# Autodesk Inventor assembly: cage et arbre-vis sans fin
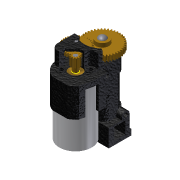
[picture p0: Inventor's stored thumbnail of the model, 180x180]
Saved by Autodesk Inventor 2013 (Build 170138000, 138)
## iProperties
Created: 2011-10
Part Number: cage et arbre-vis sans fin
Document SubType Name: Assembly
Designer: didierf
Author: didierf
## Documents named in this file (8)
- D:\_an13-14\FORMULAIRE_2014\Sujet E4 Poissy 2014\Modélisation_7970_shimano_2014\cage et arbre-vis sans fin.iam
- D:\_an13-14\FORMULAIRE_2014\Sujet E4 Poissy 2014\Modélisation_7970_shimano_2014\cage_moto_reducteur.ipt
- D:\_an13-14\FORMULAIRE_2014\Sujet E4 Poissy 2014\Modélisation_7970_shimano_2014\Mobile vis sans fin.iam
- D:\_an13-14\FORMULAIRE_2014\Sujet E4 Poissy 2014\Modélisation_7970_shimano_2014\Butée axiale vis sans fin.ipt
- D:\_an13-14\FORMULAIRE_2014\Sujet E4 Poissy 2014\Modélisation_7970_shimano_2014\axe engr_cyl inter.ipt
- D:\_an13-14\FORMULAIRE_2014\Sujet E4 Poissy 2014\Modélisation_7970_shimano_2014\Mobile intermédiaire 37 dents m0,25 - 10 dents m0,3.iam
- D:\_an13-14\FORMULAIRE_2014\Sujet E4 Poissy 2014\Modélisation_7970_shimano_2014\moteur DC.ipt
- D:\_an13-14\FORMULAIRE_2014\Sujet E4 Poissy 2014\Modélisation_7970_shimano_2014\arbre moteur et pignon 11 dents m0,25.iam
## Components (7 placed, 7 different names)
1. cage_moto_reducteur:1 — position axiale vis / cage, coaxialité axe inter / cage, Affleurement axe inter / cage, butée axiale mobile inter / cage, Affleurement:3, Angle:2, pos1 butée axiale, pos2 butée axiale, pos3 butée axiale
2. Mobile vis sans fin:1 [sub-assembly] — position axiale vis / cage, Rotation:1, Placage:8
3. Butée axiale vis sans fin:1 — pos1 butée axiale, pos2 butée axiale, pos3 butée axiale
4. axe engr_cyl inter:1 — coaxialité axe inter / cage, Affleurement axe inter / cage, coaxialité axe inter / mobile inter
5. Mobile intermédiaire 37 dents m0,25 - 10 dents m0,3:1 [sub-assembly] — coaxialité axe inter / mobile inter, butée axiale mobile inter / cage, Rotation:1, Rotation:2
6. moteur DC:1 — Affleurement:3, coaxialité arbre moteur, position axiale arbre moteur
7. arbre moteur et pignon 11 dents m0,25:1 [sub-assembly] — coaxialité arbre moteur, position axiale arbre moteur, Rotation:2
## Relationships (15: Mate 10, Flush 2, RelateRotation 2, Angle 1)
- position axiale vis / cage [Mate]: cage_moto_reducteur:1 ↔ Mobile vis sans fin:1
- coaxialité axe inter / cage [Mate]: cage_moto_reducteur:1 ↔ axe engr_cyl inter:1
- Affleurement axe inter / cage [Flush]: cage_moto_reducteur:1 ↔ axe engr_cyl inter:1
- coaxialité axe inter / mobile inter [Mate]: axe engr_cyl inter:1 ↔ Mobile intermédiaire 37 dents m0,25 - 10 dents m0,3:1
- butée axiale mobile inter / cage [Mate]: cage_moto_reducteur:1 ↔ Mobile intermédiaire 37 dents m0,25 - 10 dents m0,3:1
- Rotation:1 [RelateRotation]: Mobile vis sans fin:1 ↔ Mobile intermédiaire 37 dents m0,25 - 10 dents m0,3:1
- Affleurement:3 [Flush]: cage_moto_reducteur:1 ↔ moteur DC:1
- coaxialité arbre moteur [Mate]: moteur DC:1 ↔ arbre moteur et pignon 11 dents m0,25:1
- position axiale arbre moteur [Mate]: moteur DC:1 ↔ arbre moteur et pignon 11 dents m0,25:1
- Rotation:2 [RelateRotation]: Mobile intermédiaire 37 dents m0,25 - 10 dents m0,3:1 ↔ arbre moteur et pignon 11 dents m0,25:1
- Placage:8 [Mate]: Mobile vis sans fin:1
- Angle:2: cage_moto_reducteur:1
- pos1 butée axiale [Mate]: cage_moto_reducteur:1 ↔ Butée axiale vis sans fin:1
- pos2 butée axiale [Mate]: cage_moto_reducteur:1 ↔ Butée axiale vis sans fin:1
- pos3 butée axiale [Mate]: cage_moto_reducteur:1 ↔ Butée axiale vis sans fin:1
